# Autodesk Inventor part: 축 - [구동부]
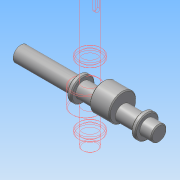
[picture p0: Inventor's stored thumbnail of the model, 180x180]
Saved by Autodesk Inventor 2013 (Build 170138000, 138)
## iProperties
Company: 한국ATC센터
Created: 2014-08
Part Number: 축 - [구동부]
Document SubType Name: Modeling
Designer: KYOUNG IL JANG
Density: 7.86 g/cm^3
Material: 강철, 연강
Mass: 375.453 g
Surface Area: 117.38 cm^2
Volume: 47.7676 cm^3
Author: KYOUNG IL JANG
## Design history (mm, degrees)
sketch "스케치1"
  geometry: L1 (-76.5, 0)-(76.5, 0); L2 (-76.5, 0)-(-76.5, 8.5); L3 (-76.5, 8.5)-(-12.5, 8.5); L4 (-12.5, 8.5)-(-12.5, 13); L5 (-12.5, 13)-(-7.5, 13); L6 (-7.5, 13)-(-7.5, 8.5); L7 (-7.5, 8.5)-(58.5, 8.5); L8 (58.5, 8.5)-(58.5, 13); L9 (58.5, 13)-(63.5, 13); L10 (63.5, 13)-(63.5, 8.5); L11 (63.5, 8.5)-(76.5, 8.5); L12 (76.5, 8.5)-(76.5, 0); 2 further points
  constraints: 24 end point, 5 parallel, 1 coincident, 1 horizontal, 1 midpoint, 1 perpendicular
  dimensions: "d0" = 153 distance of L1.start L1.end (derived); "d2" = 17 diameter of L3 L1; "d3" = 26 diameter of L5 L1; "d4" = 17 diameter of L7 L1; "d5" = 26 diameter of L9 L1; "d6" = 17 diameter of L11 L1; "d7" = 5 distance of L8.end L9.end; "d8" = 5 distance of L4.end L5.end; "d10" = 64 distance of L2.end L3.end; "d11" = 13 distance of L10.end L11.end; "d35" = 66 distance between parallel lines of L8 L6
revolve "회전1" sketch "스케치1" stored, may be unused: angle "d12" = 90 deg
node "작업 평면1"
node "작업 평면2"
node "작업 평면4"
sketch "스케치6"
  geometry: C1 r 15 at (-5, -6); 1 further point
  constraints: 1 centre point, 1 horizontal alignment
  dimensions: "d31" = 30 diameter of C1; "d32" = 5 distance of C1.centre point (0, -6)
extrude "돌출4" join sketch "스케치6" stored distance "d33" = 22; taper "d34" = 0 deg
node "작업 평면3"
sketch "스케치5"
  geometry: L1 (32, 8.5)-(32, -8.5) reference; L2 (32, -2.5)-(14.5, -2.5); L3 (14.5, 2.5)-(32, 2.5); A1 r 2.5 centre (14.5, 0) between (14.5, 2.5) and (14.5, -2.5); 2 further points
  constraints: 4 end point, 2 point on circle, 2 point on line, 2 tangent, 1 centre point, 1 midpoint, 1 parallel, 1 perpendicular
  dimensions: "d23" = 5 distance between parallel lines of L3 L2; "d36" = 20 dimension on A1 L1
extrude "돌출3" cut sketch "스케치5" distance "d25" = 3; taper "d26" = 0 deg
chamfer "모따기1" distance "d27" = 1; stored, may be unused: second distance "d28" = 2, angle "d29" = 45 deg
node "솔리드1"
other parameters: "d13" = 9.5, "d18" = 9.5
